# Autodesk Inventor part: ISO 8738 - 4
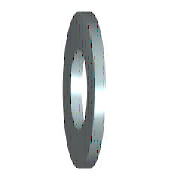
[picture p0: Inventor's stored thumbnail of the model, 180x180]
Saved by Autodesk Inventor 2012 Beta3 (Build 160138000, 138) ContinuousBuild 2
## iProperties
Created: 2010-11
Part Number: ISO 8738 - 4
Material: Steel
Description: Washer
Document SubType Name: Modeling
Standard: ISO 8738
Designer: Beta-8540w
Standard Revision: 1992
Standards Organization: DIN
Language: en-US
Size Designation: 4
Categories: <MemberInstance><Categories><Category DisplayName="Fasteners" InternalName="e4da775c-781d-43d5-af7c-5136215cf5a6" Mnemonic="FSTN"><Category DisplayName="Washers
Density: 7.85 g/cm^3
IsCustomPart: 0
Author: Beta-8540w
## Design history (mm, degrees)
body "Solid1"
sketch "Sketch"
  geometry: C1 r 4 at (0, 0); C2 r 2 at (0, 0); 1 further point
  constraints: 2 centre point, 2 coincident
  dimensions: "d0" = 4 diameter of C2 (= SD1); "d1" = 8 diameter of C1 (= SD2)
extrude "Body" new body sketch "Sketch" distance "d2" = 0.8 (= SD); taper "d3" = 0 deg
workaxis "Work Axis1"
workplane "Work Plane1"
other parameters: "SD1" = 4 [user parameter; used in 1 equation term], "SD2" = 8 [user parameter; used in 1 equation term], "SD" = 0.8 [user parameter; used in 1 equation term], "d4" = 0, "d5" = 0, "d6" = 0, "d7" = 0, "NND" = 4 [user parameter]
